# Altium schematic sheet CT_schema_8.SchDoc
size 278 x 170 mm
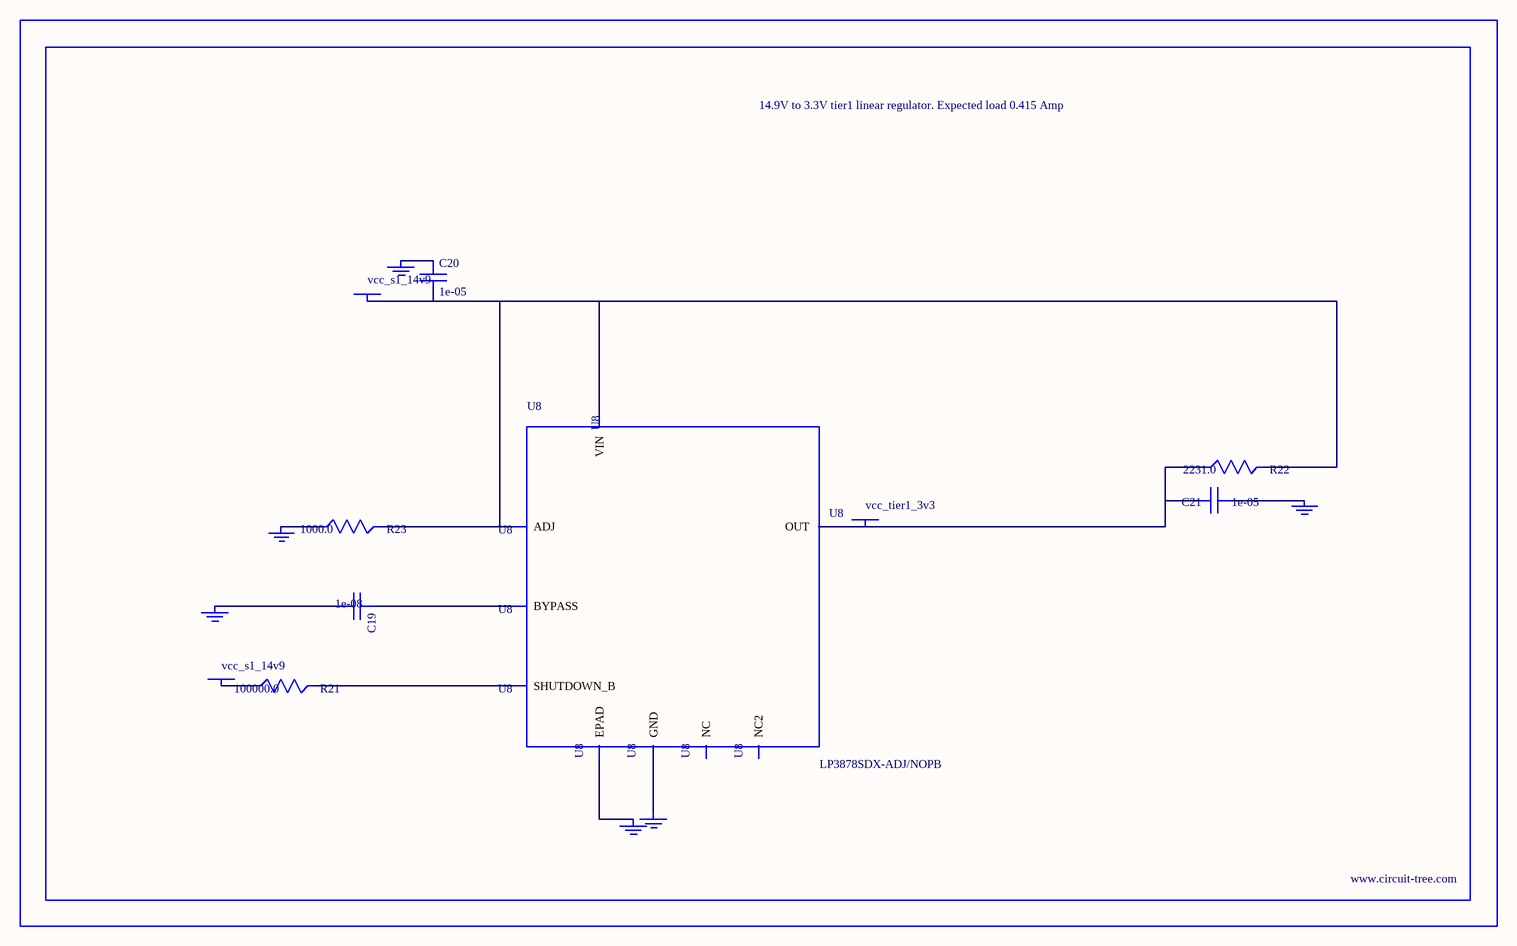
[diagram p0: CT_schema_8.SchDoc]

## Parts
BORDER7  (no value)
C19  1e-08  [C0402]
C20  1e-05  [C1210]
C21  1e-05  [C1210]
GND_INSTANCE_7_0  (no value)
GND_INSTANCE_7_1  (no value)
GND_INSTANCE_7_2  (no value)
GND_INSTANCE_7_3  (no value)
GND_INSTANCE_7_4  (no value)
GND_INSTANCE_7_5  (no value)
POWER_INSTANCE_7_0  vcc_s1_14v9
POWER_INSTANCE_7_1  vcc_s1_14v9
POWER_INSTANCE_7_2  vcc_tier1_3v3
R21  100000.0  [R0603]
R22  2231.0  [R0603]
R23  1000.0  [R0603]
U8  LP3878SDX-ADJ/NOPB  [WSON-8]

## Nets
NetC19_1: C19.1 U8.1(BYPASS)
NetC19_2: C19.2 GND_INSTANCE_7_0.0(GND)
NetC20_1: C20.1 GND_INSTANCE_7_1.0(GND)
NetC20_2: C20.2 POWER_INSTANCE_7_0.0(PWR) R22.2 R23.2 U8.4(VIN) U8.6(ADJ)
NetC21_1: C21.1 GND_INSTANCE_7_2.0(GND)
NetC21_2: C21.2 POWER_INSTANCE_7_2.0(PWR) R22.1 U8.5(OUT)
NetGND_INSTANCE_7_3_0: GND_INSTANCE_7_3.0(GND) R23.1
NetGND_INSTANCE_7_4_0: GND_INSTANCE_7_4.0(GND) U8.PAD(EPAD)
NetGND_INSTANCE_7_5_0: GND_INSTANCE_7_5.0(GND) U8.3(GND)
NetPOWER_INSTANCE_7_1_0: POWER_INSTANCE_7_1.0(PWR) R21.1
NetR21_2: R21.2 U8.8(SHUTDOWN_B)

Not connected (* = marked no-connect by the designer): U8 2(NC) 7(NC2)

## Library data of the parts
BORDER7 = BORDER_PAGE7
C19 = C0402C103K3RAC
C20 = C1210C106K5PACTU
C21 = GRM32DR61E106MA12L
GND_INSTANCE_7_0-GND_INSTANCE_7_5 = GND
POWER_INSTANCE_7_0-POWER_INSTANCE_7_2 = PWR
R21 = RC0603JR-07100KL
R22 = R22
R23 = RC0603JR-071KL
